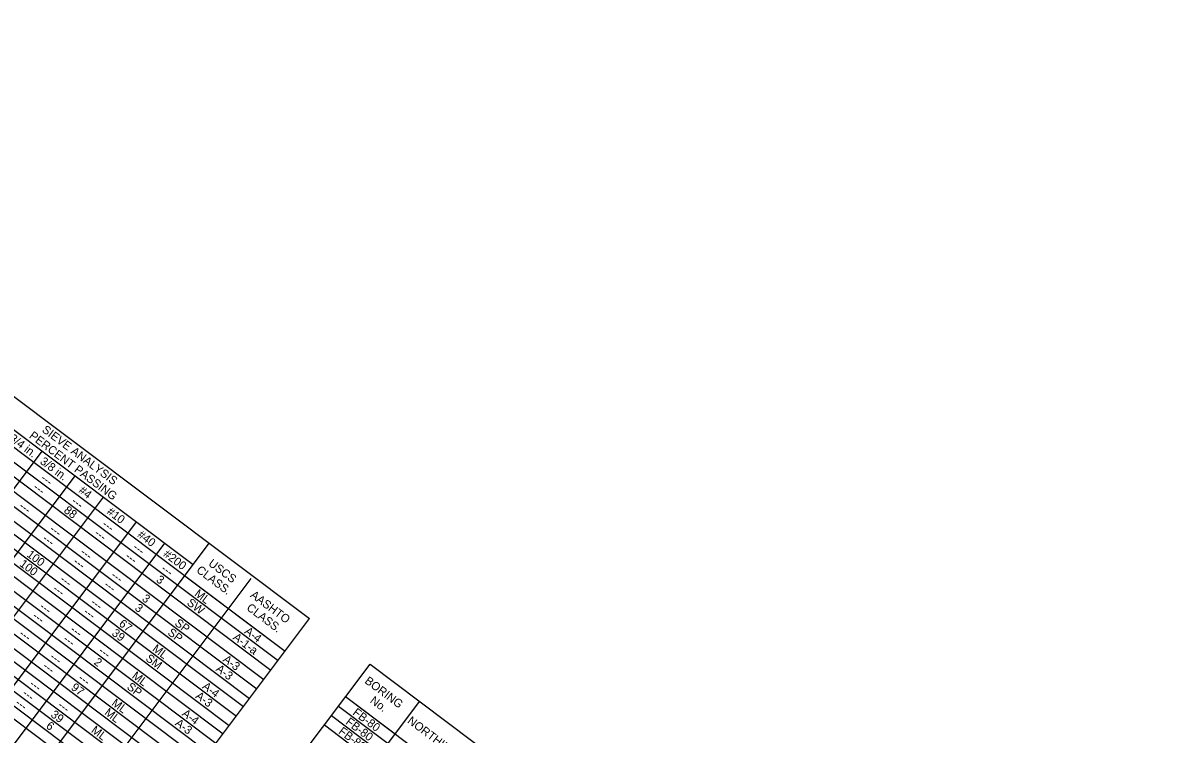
# Model space of a CAD drawing. Extents: x 627484.2 to 627514.4, y 367972.1 to 367996.9.
# Drawn here: x 627490.82 to 627498.35, y 367992.21 to 367996.91 of the extents above; entities that cross this region are included whole.
import ezdxf

# ---------------------------------------------------------------- set-up
doc = ezdxf.new("R2010")
doc.units = 0
doc.layers.add('Default', color=7, linetype='Continuous')
doc.layers.add('R_Survey Control', color=7, linetype='Continuous')

msp = doc.modelspace()

# ---------------------------------------------------------------- linework, layer by layer
at = {"layer": 'Default'}
for p, q in [((627487.4706, 367996.9059), (627492.71, 367992.9716)), ((627487.3096, 367996.6915), (627492.549, 367992.7571)), ((627487.2159, 367996.5667), (627492.4553, 367992.6324)), ((627487.2628, 367996.6291), (627492.5022, 367992.6948)), ((627487.1691, 367996.5044), (627492.4085, 367992.57)), ((627487.1223, 367996.442), (627492.3617, 367992.5077)), ((627487.0754, 367996.3796), (627492.3148, 367992.4453)), ((627486.9876, 367996.2627), (627492.227, 367992.3283)), ((627487.0344, 367996.325), (627492.2739, 367992.3907)), ((627486.9408, 367996.2003), (627492.1802, 367992.266)), ((627486.8998, 367996.1457), (627492.1392, 367992.2114)), ((627486.8529, 367996.0833), (627492.0924, 367992.149)), ((627486.7651, 367995.9664), (627492.0045, 367992.0321)), ((627486.8061, 367996.021), (627492.0455, 367992.0866)), ((627486.7183, 367995.904), (627491.9577, 367991.9697)), ((627486.6715, 367995.8416), (627491.9109, 367991.9073)), ((627486.6305, 367995.7871), (627491.8699, 367991.8527)), ((627486.5368, 367995.6623), (627491.7762, 367991.728)), ((627486.5836, 367995.7247), (627491.8231, 367991.7904)), ((627486.49, 367995.5999), (627491.7294, 367991.6656)), ((627486.449, 367995.5454), (627491.6884, 367991.611)), ((627490.3514, 367994.5232), (627491.9419, 367993.3289)), ((627489.2022, 367991.7587), (627490.944, 367994.0782)), ((627489.4205, 367991.5948), (627491.1623, 367993.9143)), ((627489.6077, 367991.4543), (627491.3494, 367993.7738)), ((627489.826, 367991.2904), (627491.5677, 367993.6099)), ((627490.0131, 367991.1499), (627491.7548, 367993.4694)), ((627490.2002, 367991.0094), (627492.0473, 367993.4692)), ((627491.8863, 367993.2548), (627492.549, 367992.7571)), ((627490.4887, 367990.7927), (627492.3241, 367993.237)), ((627490.9039, 367990.5663), (627492.71, 367992.9716)), ((627491.1222, 367990.0244), (627493.1098, 367992.6713)), ((627493.1098, 367992.6713), (627498.3493, 367988.737)), ((627491.4501, 367989.7782), (627493.4377, 367992.4251)), ((627492.9488, 367992.4569), (627498.1883, 367988.5226)), ((627492.902, 367992.3945), (627498.1414, 367988.4602)), ((627492.8083, 367992.2698), (627498.0477, 367988.3355)), ((627492.8552, 367992.3322), (627498.0946, 367988.3978))]:
    msp.add_line(p, q, dxfattribs=at)
at = {"layer": 'R_Survey Control'}
msp.add_line((627492.9488, 367992.4569), (627493.2767, 367992.2107), dxfattribs=at)

# ---------------------------------------------------------------- texts
at = {"layer": 'Default'}
for s, p in [('SIEVE ANALYSIS', (627490.9387, 367994.2091)), ('3/4 in.', (627490.7225, 367994.1522)), ('PERCENT PASSING', (627490.8539, 367994.1696)), ('3/8 in.', (627490.9252, 367994)), ('---', (627490.8795, 367993.8301)), ('---', (627490.9299, 367993.8898)), ('#4', (627491.1803, 367993.8085)), ('---', (627490.7859, 367993.7053)), ('88', (627491.0828, 367993.6774)), ('---', (627491.1326, 367993.7376)), ('#10', (627491.3666, 367993.6686)), ('---', (627490.9886, 367993.5531)), ('---', (627491.3353, 367993.5854)), ('#40', (627491.5693, 367993.5164)), ('---', (627490.9418, 367993.4907)), ('---', (627491.285, 367993.5256)), ('100', (627490.8375, 367993.3861)), ('---', (627491.1913, 367993.4009)), ('---', (627491.538, 367993.4332)), ('#200', (627491.7401, 367993.3881)), ('100', (627490.7907, 367993.3237)), ('---', (627491.1445, 367993.3385)), ('---', (627491.4877, 367993.3734)), ('USCS', (627492.0375, 367993.3261)), ('---', (627491.394, 367993.2487)), ('3', (627491.6924, 367993.2197)), ('---', (627491.7251, 367993.2926)), ('CLASS.', (627491.9582, 367993.2825)), ('---', (627491.0098, 367993.1592)), ('---', (627491.0566, 367993.2216)), ('---', (627491.3472, 367993.1863)), ('3', (627491.5988, 367993.0949)), ('SW', (627491.8953, 367993.0673)), ('ML', (627491.9461, 367993.1267)), ('AASHTO', (627492.3145, 367993.1181)), ('---', (627490.922, 367993.0422)), ('---', (627491.2125, 367993.007)), ('---', (627491.2594, 367993.0693)), ('3', (627491.5519, 367993.0325)), ('CLASS.', (627492.2896, 367993.0337)), ('---', (627490.8752, 367992.9799)), ('67', (627491.4466, 367992.9287)), ('SP', (627491.8151, 367992.9324)), ('---', (627490.7873, 367992.8629)), ('---', (627491.1247, 367992.89)), ('39', (627491.3997, 367992.8664)), ('SP', (627491.7683, 367992.8701)), ('A-1-a', (627492.1994, 367992.8389)), ('A-4', (627492.2761, 367992.8789)), ('---', (627491.0779, 367992.8276)), ('ML', (627491.6674, 367992.7629)), ('---', (627490.99, 367992.7107)), ('---', (627491.3118, 367992.7495)), ('SM', (627491.6224, 367992.6992)), ('A-3', (627492.1336, 367992.6933)), ('---', (627490.9432, 367992.6483)), ('2', (627491.2813, 367992.6749)), ('A-3', (627492.0868, 367992.6309)), ('---', (627491.1772, 367992.5702)), ('ML', (627491.5328, 367992.5836)), ('BORING', (627493.0699, 367992.5508)), ('---', (627490.8554, 367992.5314)), ('97', (627491.1305, 367992.5077)), ('SP', (627491.499, 367992.5114)), ('A-4', (627491.9974, 367992.5151)), ('---', (627490.7617, 367992.4066)), ('---', (627490.8086, 367992.469)), ('ML', (627491.3981, 367992.4043)), ('A-3', (627491.9522, 367992.4516)), ('No.', (627493.1055, 367992.4209)), ('39', (627490.9957, 367992.3284)), ('---', (627491.0425, 367992.3909)), ('ML', (627491.3513, 367992.3419)), ('A-4', (627491.8628, 367992.3358)), ('FB-80', (627492.991, 367992.3421)), ('6', (627490.965, 367992.254)), ('ML', (627491.2635, 367992.225)), ('A-3', (627491.8175, 367992.2722)), ('FB-80', (627492.9441, 367992.2797)), ('NORTHING', (627493.3522, 367992.2873)), ('FB-80', (627492.8973, 367992.2174))]:
    msp.add_text(s, height=0.055, rotation=323.09678, dxfattribs=at).set_placement(p)

doc.saveas('drawing.dxf')
